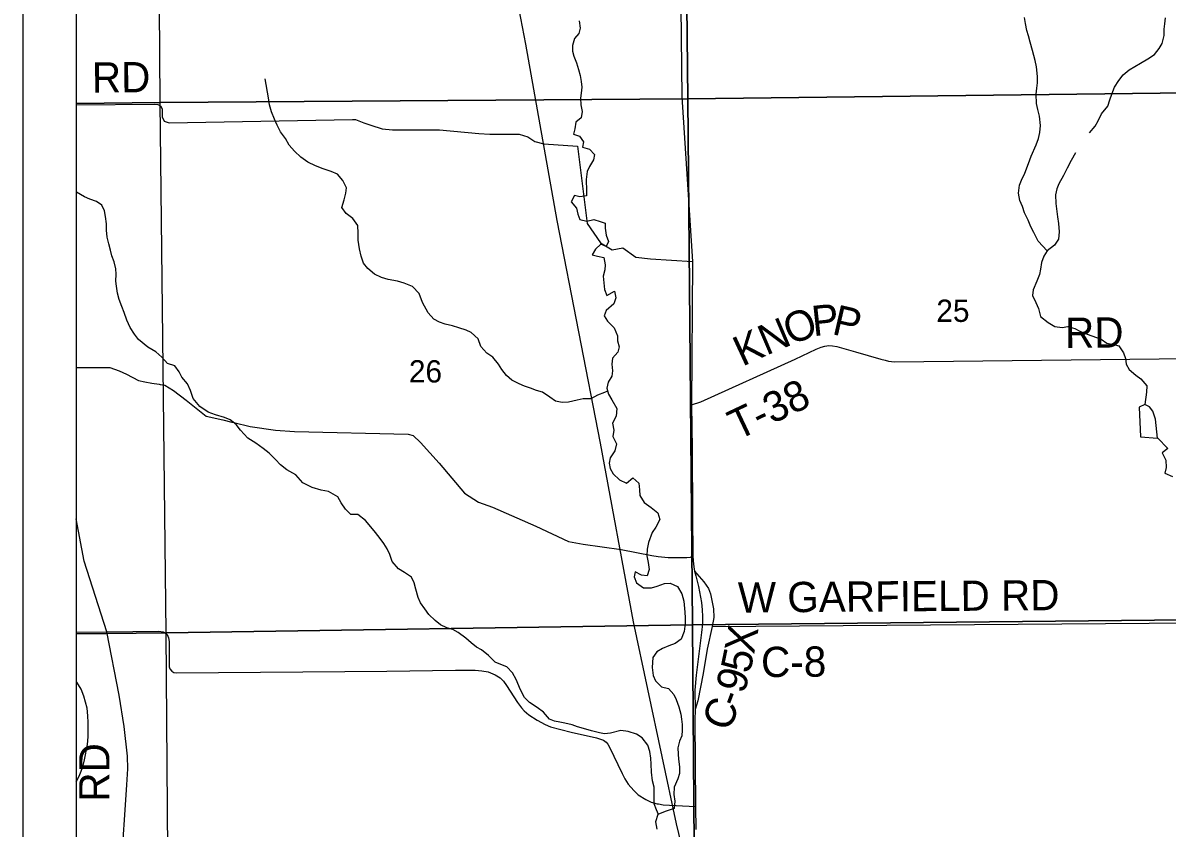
# Model space of a CAD drawing. Extents: x 0 to 36.9, y 0 to 22.
# Drawn here: x 2 to 4.148, y 15.071 to 16.582 of the extents above; entities that cross this region are included whole.
import ezdxf

# ---------------------------------------------------------------- set-up
doc = ezdxf.new("R2010")
doc.units = 0
for name, color, linetype in [('Default', 7, 'Continuous'), ('GM_X_County_Road', 7, 'Continuous'), ('GM_X_County_Road_Text', 7, 'Continuous'), ('GM_X_Minor_Lake', 7, 'Continuous'), ('GM_X_Minor_River', 7, 'Continuous'), ('GM_X_Rail_Line', 7, 'Continuous'), ('GM_X_Section', 7, 'Continuous'), ('GM_X_Section_Text', 7, 'Continuous'), ('GM_X_Township_Road', 7, 'Continuous'), ('GM_X_Township_Road_Text', 7, 'Continuous'), ('SH_Cut_Line', 7, 'Continuous'), ('SH_Data', 7, 'Continuous')]:
    doc.layers.add(name, color=color, linetype=linetype)

msp = doc.modelspace()

# ---------------------------------------------------------------- linework, layer by layer
at = {"layer": 'Default'}
for points in [[(2.1, 17.4248), (2.1, 16.4306), (2.2574, 16.4325), (2.2509, 17.4272)], [(2.1, 16.4306), (2.1, 15.4352), (2.2688, 15.4372), (2.2574, 16.4325)], [(2.1, 15.4352), (2.1, 14.4458), (2.2767, 14.4483), (2.2688, 15.4372)]]:
    msp.add_lwpolyline(points, close=True, dxfattribs=at)
at = {"layer": 'GM_X_County_Road'}
msp.add_line((3.2939, 15.4488), (4.2488, 15.4562), dxfattribs=at)
for points in [[(3.232, 16.893), (3.2368, 16.4429), (3.2568, 16.1339), (3.255, 15.8649), (3.2563, 15.7816), (3.257, 15.6575), (3.2577, 15.5814), (3.258, 15.5726), (3.2595, 15.5608), (3.2608, 15.5526), (3.2629, 15.544), (3.2678, 15.5244), (3.2738, 15.4944), (3.2751, 15.4806), (3.2759, 15.4678), (3.2756, 15.4538), (3.2739, 15.438), (3.2637, 15.3578), (3.2614, 15.3296), (3.2616, 15.2931), (3.261, 15.2734), (3.2626, 15.1115), (3.2634, 15.0681)], [(2.1833, 14.9764), (2.1842, 14.9933), (2.1948, 15.152), (2.1971, 15.1817), (2.1961, 15.2059), (2.1903, 15.2612), (2.1808, 15.3203), (2.1573, 15.4391), (2.1152, 15.5714), (2.1, 15.651)], [(3.2608, 15.5526), (3.278, 15.5331), (3.2871, 15.5203), (3.2906, 15.5105), (3.2965, 15.482), (3.2967, 15.4661), (3.2939, 15.4488), (3.2841, 15.4064), (3.2766, 15.361), (3.2668, 15.3097), (3.2616, 15.2931)]]:
    msp.add_lwpolyline(points, dxfattribs=at)
at = {"layer": 'GM_X_Minor_Lake'}
for points in [[(4.1295, 15.8027), (4.1259, 15.8383), (4.1207, 15.853), (4.1145, 15.8613), (4.1061, 15.8657), (4.0951, 15.8606), (4.0979, 15.8048)], [(4.0979, 15.8048), (4.1295, 15.8027)]]:
    msp.add_lwpolyline(points, dxfattribs=at)
at = {"layer": 'GM_X_Minor_River'}
for points in [[(3.0442, 16.5855), (3.0463, 16.5722), (3.0434, 16.5623), (3.0356, 16.5527), (3.0313, 16.5397), (3.0315, 16.5291), (3.0343, 16.5192), (3.0394, 16.5068), (3.0427, 16.4943), (3.0459, 16.483), (3.048, 16.472), (3.0489, 16.4614), (3.048, 16.4503), (3.0466, 16.4404), (3.0472, 16.4283), (3.0497, 16.4154), (3.048, 16.4036), (3.0379, 16.3955), (3.0358, 16.3833), (3.0333, 16.373), (3.0448, 16.369), (3.0522, 16.3588)], [(3.9226, 16.1542), (3.9056, 16.1722), (3.8974, 16.1884), (3.8919, 16.1993), (3.8867, 16.2117), (3.8797, 16.2257), (3.8761, 16.237), (3.8713, 16.2487), (3.8688, 16.2623), (3.8708, 16.2772), (3.8741, 16.2867), (3.8803, 16.2998), (3.8876, 16.3181), (3.8927, 16.3315), (3.9018, 16.3529), (3.9062, 16.3651), (3.9087, 16.3762), (3.91, 16.3891), (3.9082, 16.4066), (3.9053, 16.4191), (3.9028, 16.4308), (3.9021, 16.4479), (3.9031, 16.4597), (3.9041, 16.4696), (3.9043, 16.481), (3.9024, 16.4992), (3.9, 16.5113), (3.8947, 16.5302), (3.8906, 16.5457), (3.8874, 16.5574), (3.8842, 16.5676), (3.8817, 16.5805), (3.88, 16.5919)], [(4.0022, 16.3754), (4.0126, 16.3881), (4.0181, 16.3984), (4.0247, 16.4115), (4.0366, 16.4257), (4.0402, 16.4372), (4.0441, 16.4483), (4.0492, 16.4613), (4.057, 16.4739), (4.0651, 16.4847), (4.0767, 16.494), (4.0872, 16.5003), (4.0978, 16.5062), (4.1117, 16.5144), (4.1237, 16.5226), (4.1326, 16.5337), (4.1385, 16.5433), (4.142, 16.5582), (4.1422, 16.5704), (4.1431, 16.5802), (4.1448, 16.5913)], [(3.0976, 15.8906), (3.0919, 15.8881), (3.0783, 15.8833), (3.0659, 15.8766), (3.0518, 15.8764), (3.0401, 15.8736), (3.0239, 15.8703), (3.0125, 15.8697), (2.9999, 15.8722), (2.9892, 15.8792), (2.9753, 15.8888), (2.9639, 15.8917), (2.9528, 15.8961), (2.9414, 15.9001), (2.9314, 15.9048), (2.9176, 15.9111), (2.908, 15.9204), (2.8991, 15.9317), (2.8925, 15.9414), (2.882, 15.9546), (2.8705, 15.9623), (2.8593, 15.9747), (2.8545, 15.9887), (2.8417, 16.001), (2.8322, 16.005), (2.8184, 16.0094), (2.8066, 16.0133), (2.7929, 16.0162), (2.7822, 16.0202), (2.7711, 16.0257), (2.7606, 16.038), (2.7501, 16.0572), (2.7437, 16.0739), (2.731, 16.0869), (2.7157, 16.0935), (2.7031, 16.0971), (2.6856, 16.1003), (2.6734, 16.1042), (2.66, 16.1105), (2.6473, 16.1209), (2.6395, 16.1307), (2.6347, 16.1439), (2.6318, 16.1579), (2.6293, 16.1742), (2.6295, 16.1871), (2.6285, 16.2019), (2.6195, 16.2147), (2.6068, 16.2239), (2.5987, 16.2352), (2.603, 16.2501), (2.6062, 16.2623), (2.6075, 16.2722), (2.6005, 16.2861), (2.5904, 16.2977), (2.5789, 16.3033), (2.5637, 16.3083), (2.5491, 16.3138), (2.5346, 16.3208), (2.5219, 16.3301), (2.51, 16.3409), (2.4999, 16.3525), (2.4929, 16.3649), (2.4835, 16.3777), (2.4773, 16.3897), (2.4721, 16.401), (2.4666, 16.415), (2.4629, 16.4282), (2.4616, 16.4377), (2.4591, 16.4517), (2.4566, 16.4661), (2.4545, 16.4767)], [(3.0522, 16.3588), (3.0504, 16.3489), (3.0634, 16.345), (3.0727, 16.3349), (3.0713, 16.3246), (3.0636, 16.3123), (3.0592, 16.3027), (3.0575, 16.2879), (3.0579, 16.2666), (3.0576, 16.2571), (3.0455, 16.2554), (3.0352, 16.2579), (3.029, 16.246), (3.0394, 16.234), (3.0419, 16.2227), (3.0455, 16.2129), (3.0584, 16.2096), (3.0717, 16.2129), (3.0835, 16.2093), (3.093, 16.206), (3.0928, 16.1965), (3.0949, 16.1837), (3.0993, 16.1719), (3.0945, 16.1624), (3.085, 16.1668), (3.0745, 16.1571), (3.0686, 16.1464), (3.0785, 16.1439), (3.0903, 16.1418), (3.0928, 16.1278), (3.0922, 16.1183), (3.089, 16.1064), (3.0917, 16.0814), (3.0961, 16.0705), (3.1104, 16.0787), (3.1132, 16.0658), (3.1089, 16.0544), (3.095, 16.042), (3.091, 16.0324), (3.0972, 16.0223), (3.11, 16.0095), (3.1163, 15.9948), (3.1161, 15.985), (3.1189, 15.974), (3.1168, 15.9641), (3.1068, 15.9525), (3.1054, 15.9415), (3.1064, 15.929), (3.1054, 15.9187), (3.0988, 15.9079), (3.0959, 15.8961), (3.0991, 15.8852), (3.1054, 15.8743), (3.1148, 15.8581), (3.1135, 15.844), (3.1065, 15.8306), (3.109, 15.8177), (3.1073, 15.8059), (3.1144, 15.792), (3.1108, 15.7786), (3.1023, 15.7656), (3.1002, 15.7557), (3.1026, 15.7458), (3.1077, 15.7353), (3.12, 15.7241), (3.1331, 15.7178), (3.145, 15.7283), (3.1558, 15.7182), (3.1572, 15.7057), (3.1577, 15.6947), (3.1663, 15.6819), (3.1794, 15.6726), (3.1917, 15.6626), (3.1953, 15.6501), (3.1883, 15.6352), (3.1813, 15.6252), (3.1744, 15.6065), (3.1719, 15.5943), (3.1714, 15.5814), (3.1735, 15.5692), (3.1752, 15.5563), (3.172, 15.5441), (3.1614, 15.5451), (3.1495, 15.5517), (3.1474, 15.5422), (3.1517, 15.5313), (3.1648, 15.5216), (3.18, 15.5215), (3.1905, 15.5247), (3.2045, 15.5299), (3.2147, 15.5304), (3.2285, 15.5242), (3.2371, 15.5106), (3.2404, 15.4963), (3.2422, 15.4758), (3.2432, 15.4652), (3.243, 15.4549), (3.2413, 15.4397), (3.2355, 15.4255), (3.2242, 15.417), (3.2125, 15.4126)], [(3.9754, 16.3378), (3.9676, 16.3236), (3.9603, 16.3094), (3.9529, 16.2956), (3.9444, 16.2799), (3.9404, 16.2703), (3.9383, 16.2589), (3.9386, 16.243), (3.9404, 16.2278), (3.9417, 16.2179), (3.9438, 16.2051), (3.9452, 16.1895), (3.9435, 16.1762), (3.9361, 16.1647), (3.9226, 16.1542), (3.916, 16.1442), (3.9116, 16.1324), (3.9103, 16.1198), (3.9082, 16.1099), (3.9031, 16.0969), (3.8961, 16.0808), (3.8948, 16.0702), (3.9015, 16.057), (3.9062, 16.0461), (3.9099, 16.0309), (3.9245, 16.0194), (3.9371, 16.0124), (3.9508, 16.0103), (3.9614, 16.012), (3.9744, 16.0084), (3.984, 16.0036), (3.9974, 15.9974)], [(2.1952, 16.0239), (2.1904, 16.0386), (2.1857, 16.0499), (2.1809, 16.0628), (2.1777, 16.0749), (2.1759, 16.0878), (2.1746, 16.0972), (2.1748, 16.1105), (2.1746, 16.1204), (2.1714, 16.1336), (2.167, 16.1446), (2.1642, 16.1552), (2.1613, 16.1673), (2.1581, 16.1798), (2.1567, 16.193), (2.1569, 16.2048), (2.1552, 16.2185), (2.1531, 16.2291), (2.148, 16.24), (2.138, 16.2467), (2.1258, 16.251), (2.1154, 16.2554), (2.1009, 16.2643), (2.1, 16.2651)], [(3.1932, 15.0965), (3.1891, 15.105), (3.1852, 15.1163), (3.185, 15.127), (3.1852, 15.1383), (3.1846, 15.1478), (3.1818, 15.1592), (3.1796, 15.1755), (3.179, 15.1907), (3.1788, 15.2017), (3.1767, 15.2145), (3.1727, 15.2266), (3.1626, 15.2398), (3.1519, 15.2472), (3.1362, 15.2519), (3.1225, 15.2539), (3.1029, 15.249), (3.0919, 15.2474), (3.082, 15.2495), (3.0671, 15.253), (3.0564, 15.2566), (3.0408, 15.2606), (3.0312, 15.2642), (3.0175, 15.2678), (3.008, 15.2695), (2.9981, 15.2716), (2.9886, 15.2753), (2.9769, 15.2884), (2.965, 15.2969), (2.9512, 15.3062), (2.9416, 15.3159), (2.9341, 15.3299), (2.9258, 15.3495), (2.9192, 15.3623), (2.9083, 15.3731), (2.8969, 15.3779), (2.8862, 15.3819), (2.8742, 15.3946), (2.8611, 15.405), (2.8515, 15.4105), (2.8415, 15.4184), (2.8315, 15.4273), (2.8169, 15.4377), (2.807, 15.4432), (2.7955, 15.4465), (2.784, 15.4524), (2.7737, 15.4606), (2.7617, 15.4718), (2.7543, 15.4819), (2.7465, 15.4932), (2.7418, 15.5037), (2.7378, 15.5192), (2.7345, 15.5313), (2.7294, 15.5415), (2.7164, 15.5504), (2.7049, 15.5574), (2.6929, 15.5713), (2.6888, 15.5841), (2.6837, 15.5951), (2.6775, 15.6048), (2.6686, 15.6168), (2.6596, 15.6288), (2.643, 15.6479), (2.6288, 15.6595), (2.6158, 15.6593), (2.6058, 15.669), (2.5973, 15.6814), (2.5914, 15.6923), (2.5738, 15.7023), (2.5597, 15.7051), (2.5429, 15.7097), (2.5256, 15.7186), (2.5121, 15.7335), (2.4956, 15.7428), (2.4833, 15.7524), (2.4741, 15.7622), (2.4625, 15.7741), (2.4509, 15.7834), (2.4375, 15.7931), (2.4225, 15.8027), (2.4082, 15.8173), (2.4001, 15.8282), (2.3893, 15.8371), (2.3782, 15.8411), (2.3618, 15.8462), (2.3477, 15.8516), (2.3323, 15.862), (2.3199, 15.877), (2.3147, 15.8921), (2.3092, 15.9046), (2.2984, 15.9169), (2.2936, 15.9267), (2.2855, 15.938), (2.2714, 15.9427), (2.2609, 15.9543), (2.2494, 15.9647), (2.2344, 15.9732), (2.2171, 15.9878), (2.2093, 15.9975), (2.2011, 16.0103), (2.1952, 16.0239)], [(3.9974, 15.9974), (4.0236, 15.9885), (4.0347, 15.9808), (4.0477, 15.978), (4.0572, 15.9755), (4.0658, 15.9627), (4.0694, 15.9518), (4.0711, 15.9412), (4.0762, 15.9314), (4.0889, 15.921), (4.0986, 15.9139), (4.1094, 15.9005), (4.1089, 15.8887), (4.1061, 15.8657)], [(4.1295, 15.8031), (4.1491, 15.7831), (4.1386, 15.775), (4.1453, 15.7614), (4.146, 15.7474), (4.1435, 15.7367), (4.1577, 15.7305)], [(3.2125, 15.4126), (3.2005, 15.4079), (3.1896, 15.4012), (3.1825, 15.3909), (3.1813, 15.3722), (3.1831, 15.3571), (3.1874, 15.3469), (3.1986, 15.3357), (3.2116, 15.3325), (3.2216, 15.3216), (3.2263, 15.3118), (3.2311, 15.2982), (3.2348, 15.2846), (3.2361, 15.2751), (3.2374, 15.2653), (3.2375, 15.2547), (3.2366, 15.2436), (3.2326, 15.2337), (3.2294, 15.2211), (3.2299, 15.2097), (3.2305, 15.1999), (3.2326, 15.1858), (3.2324, 15.1729), (3.2296, 15.1634), (3.2226, 15.1477), (3.2221, 15.134), (3.2238, 15.1215), (3.2225, 15.1074), (3.2055, 15.1018), (3.192, 15.0959), (3.1876, 15.0826), (3.1897, 15.0689)], [(2.1, 15.1576), (2.1021, 15.1609), (2.1069, 15.1713), (2.1127, 15.1854), (2.1156, 15.1988), (2.1211, 15.2277), (2.1228, 15.2422), (2.1224, 15.2688), (2.1218, 15.2813), (2.1204, 15.2957), (2.1143, 15.3184), (2.1092, 15.3312), (2.1014, 15.3444), (2.1, 15.3456)]]:
    msp.add_lwpolyline(points, dxfattribs=at)
at = {"layer": 'GM_X_Rail_Line'}
for points in [[(2.1, 20.4802), (2.1, 14.4405)], [(3.2967, 14.4546), (3.2965, 14.4564), (3.2931, 14.6918), (3.2793, 14.8131), (3.2696, 14.883), (3.2534, 14.9735), (3.2441, 15.0059), (3.227, 15.0787), (3.1461, 15.4577), (3.0839, 15.7931), (3.0026, 16.211), (2.9441, 16.542), (2.925, 16.6399)]]:
    msp.add_lwpolyline(points, dxfattribs=at)
at = {"layer": 'GM_X_Section'}
for points in [[(4.2298, 17.4444), (4.2381, 16.4858), (4.2388, 16.4513), (3.2483, 16.4396), (3.2373, 17.4365)], [(2.2509, 17.4272), (3.2373, 17.4365), (3.2483, 16.4396), (2.2574, 16.4325)], [(4.2388, 16.4513), (4.2479, 15.4684), (4.2477, 15.4619), (3.2569, 15.4522), (3.2483, 16.4396)], [(2.2574, 16.4325), (3.2483, 16.4396), (3.2569, 15.4522), (2.2688, 15.4372)], [(2.2688, 15.4372), (3.2569, 15.4522), (3.2645, 14.457), (2.3157, 14.4485), (2.2767, 14.4483)], [(4.2477, 15.4619), (4.2613, 14.4673), (3.2645, 14.457), (3.2569, 15.4522)]]:
    msp.add_lwpolyline(points, close=True, dxfattribs=at)
at = {"layer": 'GM_X_Township_Road'}
msp.add_line((2.1, 15.4382), (2.1573, 15.4391), dxfattribs=at)
for points in [[(2.1, 16.4283), (2.2471, 16.4294), (2.2535, 16.4288), (2.2588, 16.4256), (2.2617, 16.42), (2.2617, 16.4054), (2.2649, 16.3976), (2.2743, 16.3946), (2.6188, 16.4003)], [(2.6188, 16.4003), (2.6245, 16.4004), (2.6401, 16.3941), (2.6529, 16.39), (2.6745, 16.383), (2.6937, 16.3812), (2.7818, 16.3812), (2.8559, 16.3742), (2.8764, 16.3731), (2.895, 16.3731), (2.9318, 16.3731), (2.9475, 16.3678), (2.961, 16.3596), (2.9779, 16.355), (3.0409, 16.3503), (3.059, 16.2056), (3.0841, 16.1689), (3.1062, 16.156), (3.1261, 16.1595), (3.1506, 16.142), (3.178, 16.1391), (3.2568, 16.1339)], [(3.255, 15.8649), (3.2722, 15.8709), (3.4495, 15.9507), (3.4891, 15.9696), (3.4985, 15.9733), (3.5054, 15.9754), (3.5127, 15.9763), (3.5199, 15.9761), (3.5279, 15.9747), (3.563, 15.9647), (3.6105, 15.9505), (3.6182, 15.9487), (3.625, 15.9472), (3.6361, 15.946), (4.2434, 15.9526)], [(2.1, 15.9349), (2.1632, 15.935), (2.1808, 15.9289), (2.1946, 15.9228), (2.2169, 15.9107), (2.2291, 15.9083), (2.2421, 15.9059), (2.2558, 15.9038), (2.2577, 15.9035)], [(2.2577, 15.9035), (2.2665, 15.9022), (2.2827, 15.8922), (2.3063, 15.8737), (2.3442, 15.8441), (2.3751, 15.8367), (2.3922, 15.8326), (2.3961, 15.8317)], [(2.3961, 15.8317), (2.4263, 15.8244), (2.474, 15.8178), (2.5098, 15.8151), (2.7229, 15.8103), (2.7324, 15.8074), (2.7464, 15.7944), (2.7814, 15.7559), (2.8286, 15.6991), (2.8552, 15.6822), (2.8816, 15.6728), (2.9629, 15.6376), (3.0244, 15.6088), (3.0519, 15.6033), (3.1228, 15.5937), (3.1806, 15.5821), (3.1925, 15.5804), (3.2113, 15.5786), (3.2461, 15.5785), (3.2529, 15.5794), (3.2577, 15.5814)], [(2.1573, 15.4391), (2.2552, 15.44), (2.263, 15.4392), (2.2672, 15.4373), (2.2709, 15.4341), (2.2735, 15.4279), (2.2746, 15.4212), (2.2743, 15.3788), (2.2748, 15.3736), (2.2761, 15.3696), (2.2793, 15.3651), (2.2832, 15.3629), (2.2882, 15.3621), (2.6834, 15.3651), (2.8121, 15.3668), (2.8491, 15.3668), (2.8615, 15.366), (2.8731, 15.3638), (2.8866, 15.3586), (2.8958, 15.353), (2.9021, 15.3466), (2.9078, 15.3385), (2.9283, 15.3067), (2.9358, 15.2963), (2.9408, 15.2905), (2.9496, 15.2835), (2.9654, 15.2733), (2.98, 15.2649), (2.9903, 15.2606), (3.0292, 15.2509), (3.0767, 15.2398), (3.0899, 15.2355), (3.0946, 15.2317), (3.098, 15.2281), (3.1013, 15.2228), (3.125, 15.1733), (3.1299, 15.1634), (3.1358, 15.1533), (3.1465, 15.141), (3.1549, 15.1333), (3.1694, 15.1242), (3.1794, 15.1196), (3.1908, 15.1163), (3.1928, 15.116)], [(3.1928, 15.116), (3.2019, 15.1145), (3.2626, 15.1115)]]:
    msp.add_lwpolyline(points, dxfattribs=at)
at = {"layer": 'SH_Cut_Line'}
msp.add_lwpolyline([(2.1, 20.9), (2.1, 14.4405)], dxfattribs=at)
at = {"layer": 'SH_Data'}
for p, q in [((2, 21), (2, 14)), ((2.1, 20.9), (2.1, 14.1))]:
    msp.add_line(p, q, dxfattribs=at)

# ---------------------------------------------------------------- texts
at = {"layer": 'GM_X_County_Road_Text'}
for s, height, rotation, p in [('W GARFIELD RD', 0.056818, 0.4422, (3.3422, 15.4751)), ('X', 0.0568, 80.0444, (3.3723, 15.3957)), ('5', 0.0568, 78.1619, (3.3647, 15.3594)), ('C-8', 0.05682, 0.459, (3.3857, 15.354)), ('9', 0.0568, 73.5389, (3.3536, 15.321)), ('C', 0.0568, 66.941, (3.3247, 15.2495)), ('-', 0.0568, 69.432, (3.344, 15.295)), ('RD', 0.05682, 90, (2.1625, 15.1203))]:
    msp.add_text(s, height=height, rotation=rotation, dxfattribs=at).set_placement(p)
at = {"layer": 'GM_X_Section_Text'}
for s, p in [('25', (3.7145, 16.0207)), ('26', (2.7245, 15.907))]:
    msp.add_text(s, height=0.04186, rotation=0, dxfattribs=at).set_placement(p)
at = {"layer": 'GM_X_Township_Road_Text'}
for s, height, rotation, p in [('RD', 0.05682, 0.4937, (2.1297, 16.4509)), ('O', 0.0568, 21.2156, (3.4409, 15.9766)), ('P', 0.0568, 6.1555, (3.4837, 15.9937)), ('P', 0.0568, 347.0471, (3.5168, 15.9982)), ('N', 0.0568, 23.0912, (3.3954, 15.9572)), ('RD', 0.05682, 0.4936, (3.9563, 15.9718)), ('K', 0.0568, 24.8347, (3.3504, 15.9363)), ('T-38', 0.05682, 25.2956, (3.3412, 15.7978))]:
    msp.add_text(s, height=height, rotation=rotation, dxfattribs=at).set_placement(p)

doc.saveas('drawing.dxf')
